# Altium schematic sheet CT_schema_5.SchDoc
size 144 x 123 mm
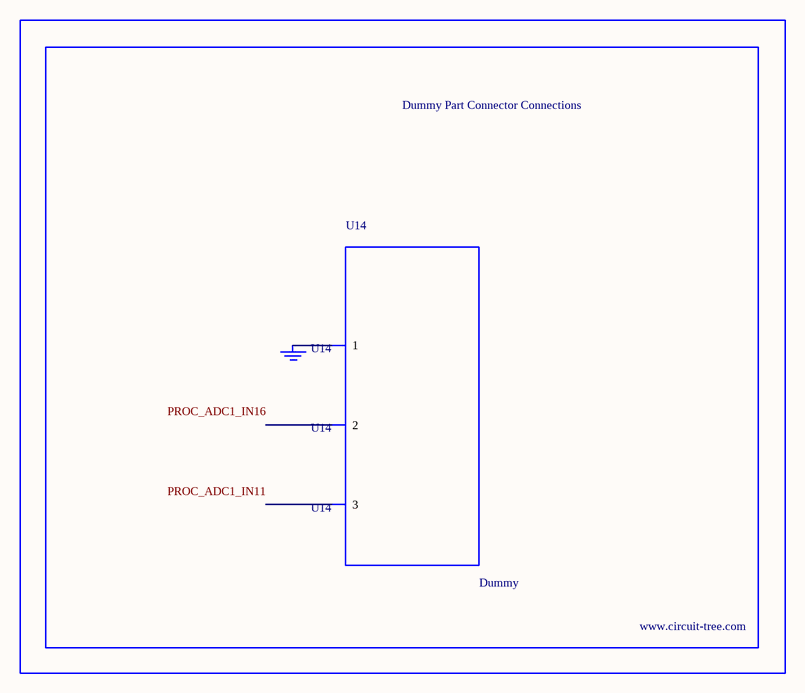
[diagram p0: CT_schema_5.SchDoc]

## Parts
BORDER4  (no value)
GND_INSTANCE_4_0  (no value)
U14  Dummy  [DUMMY_PACKAGE_132]

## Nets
NetGND_INSTANCE_4_0_0: GND_INSTANCE_4_0.0(GND) U14.1

Not connected (* = marked no-connect by the designer): U14 2 3

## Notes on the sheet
- Labels drawn without touching a wire or pin: PROC_ADC1_IN11, PROC_ADC1_IN16

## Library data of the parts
BORDER4 = BORDER_PAGE4
GND_INSTANCE_4_0 = GND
